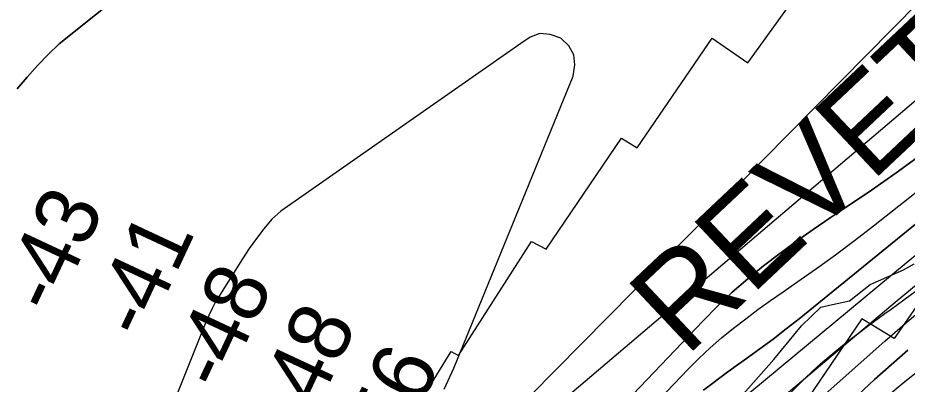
# Model space of a CAD drawing. Extents: x 3271442 to 3309282, y 752266 to 777610.
# Drawn here: x 3289820 to 3290779, y 763803 to 764198 of the extents above; entities that cross this region are included whole.
import ezdxf

# ---------------------------------------------------------------- set-up
doc = ezdxf.new("R2010")
doc.units = 0
for name, color, linetype in [('V-RIVR-EDGE', 7, 'Continuous'), ('V-RIVR-RANG', 7, 'Continuous'), ('V-RRAP-FSHR', 7, 'Continuous'), ('V-RRAP-RVMT', 7, 'Continuous'), ('V-RRAP-RVMT-IDEN', 7, 'Continuous'), ('V-TOPO-DPTH', 7, 'Continuous'), ('V-TOPO-MAJR', 7, 'Continuous'), ('V-TOPO-MINR', 7, 'Continuous'), ('V-TOPO-WATR', 7, 'Continuous')]:
    doc.layers.add(name, color=color, linetype=linetype)

msp = doc.modelspace()

# ---------------------------------------------------------------- linework, layer by layer
at = {"layer": 'V-RIVR-EDGE'}
msp.add_lwpolyline([(3290599.96, 763789.21), (3290635.27, 763829.55), (3290665.35, 763865.98), (3290686.27, 763885.93), (3290698.88, 763888.94), (3290717.15, 763892.81), (3290739.36, 763910.57), (3290775.47, 763926.13), (3290786.79, 763932.62)], dxfattribs=at)
at = {"layer": 'V-RRAP-FSHR'}
msp.add_spline([(3289175.29, 762139.24), (3289199.42, 762153.42), (3289238.78, 762167.31), (3289290.78, 762181.41), (3289361.33, 762211.47), (3289422.74, 762245.58), (3289515.55, 762307.77), (3289579.91, 762382.16), (3289624.81, 762451.54), (3289672.32, 762536.12), (3289709.18, 762613.43), (3289742.72, 762696.07), (3289778.16, 762754.9), (3289819.53, 762799.05), (3289911.37, 762921.92), (3289994.15, 763031.19), (3290081.23, 763125.2), (3290188.83, 763225.81), (3290291.39, 763333.07), (3290344.49, 763399.52), (3290388.71, 763467.2), (3290474.09, 763575.32), (3290571.03, 763693.18), (3290669.81, 763810.12), (3290775.65, 763894.02), (3290904.09, 763991.91), (3291011.39, 764077.28), (3291099.77, 764130.44), (3291153.65, 764153.45), (3291210.45, 764195.78), (3291300.74, 764249.03), (3291400.46, 764351.43), (3291483.31, 764483.33), (3291547.71, 764562.33), (3291620.77, 764622.94), (3291661.95, 764638.83), (3291706.23, 764608.33), (3291755.42, 764603.5), (3291805.88, 764628.53)], degree=3, dxfattribs=at)
at = {"layer": 'V-RRAP-RVMT'}
for points in [[(3289582.62, 762997.39), (3289626.85, 763063.65), (3289644.89, 763051.42), (3289709.27, 763155.01), (3289704.3, 763158.12), (3289783.21, 763294.08), (3289809.43, 763277.73), (3289884.41, 763395.73), (3289929.71, 763369.41), (3290001.69, 763497.83), (3290019.63, 763487.84), (3290094.58, 763611.24), (3290107.3, 763605.11), (3290184.86, 763727.23), (3290209.23, 763711.32), (3290287.31, 763838.28), (3290295.31, 763833.87), (3290373.87, 763956.68), (3290389.67, 763948.54), (3290471.14, 764068.21), (3290488.17, 764057.78), (3290568.9, 764175.9), (3290607.36, 764149.51), (3290692.59, 764267.6)], [(3290842.78, 763964.05), (3290765.31, 763852.39), (3290730.33, 763873.46), (3290651.26, 763757.1), (3290628.73, 763771.72), (3290554.34, 763656.34), (3290549.89, 763659.57), (3290471.69, 763534.96), (3290464.67, 763538.46), (3290387.65, 763416.75), (3290380.88, 763420.81), (3290304.86, 763294.94), (3290279.44, 763309.42), (3290211.6, 763193.13), (3290178.74, 763212.46), (3290105.42, 763088.04), (3290070.62, 763107.88), (3290001.82, 762986.21), (3289981.74, 762996.99), (3289899.79, 762875.03), (3289889.17, 762882.67), (3289806.67, 762757.93), (3289782.89, 762774.11)]]:
    msp.add_lwpolyline(points, dxfattribs=at)
at = {"layer": 'V-TOPO-DPTH'}
for p, q in [((3290780.02, 763839.71), (3290761.97, 763824.02)), ((3290761.97, 763824.02), (3290744.18, 763808.03)), ((3290744.18, 763808.03), (3290608.89, 763683.4))]:
    msp.add_line(p, q, dxfattribs=at)
for points in [[(3289819.2, 764121.3), (3289829.88, 764134.02), (3289840.93, 764146.44), (3289852.55, 764158.32), (3289864.54, 764169.8), (3290452.45, 764639.29)], [(3290452.45, 764639.29), (3289864.54, 764169.8), (3289852.55, 764158.32), (3289840.93, 764146.44), (3289829.88, 764134.02), (3289819.2, 764121.3)], [(3289546.72, 762768.4), (3289979.87, 763321.36), (3290007.4, 763355.22), (3290035.01, 763389), (3290062.76, 763422.68), (3290090.59, 763456.29), (3290118.71, 763489.64), (3290147.16, 763522.72), (3290176.07, 763555.38), (3290205.3, 763587.78), (3290238.78, 763624.35), (3290255.86, 763643.66), (3290272.48, 763663.35), (3290288.4, 763683.61), (3290303.86, 763704.24), (3290322.93, 763730.61), (3290328.46, 763738.38), (3290333.92, 763746.19), (3290339.27, 763754.07), (3290344.55, 763762), (3290875.23, 764299.8)], [(3290875.23, 764299.8), (3290344.55, 763762), (3290339.27, 763754.07), (3290333.92, 763746.19), (3290328.46, 763738.38), (3290322.93, 763730.61), (3290303.86, 763704.24), (3290288.4, 763683.61), (3290272.48, 763663.35), (3290255.86, 763643.66), (3290238.78, 763624.35), (3290205.3, 763587.78), (3290176.07, 763555.38), (3290147.16, 763522.72), (3290118.71, 763489.64), (3290090.59, 763456.29), (3290062.76, 763422.68), (3290035.01, 763389), (3290007.4, 763355.22), (3289979.87, 763321.36), (3289844.45, 763148.48), (3289886.98, 763122.41)], [(3290395.89, 763775.62), (3290891.68, 764197)], [(3290395.89, 763775.62), (3290891.68, 764197)], [(3290793.75, 764050.02), (3290767.39, 764030.83), (3290740.64, 764012.19), (3290713.63, 763993.9), (3290696.08, 763982.29), (3290677.8, 763969.88), (3290659.73, 763957.18), (3290641.96, 763944.06), (3290624.4, 763930.65), (3290607.32, 763916.67), (3290590.66, 763902.22), (3290574.66, 763887.05), (3290559.08, 763871.41), (3290407.9, 763712.78)], [(3290793.75, 764050.02), (3290767.39, 764030.83), (3290740.64, 764012.19), (3290713.63, 763993.9), (3290696.08, 763982.29), (3290677.8, 763969.88), (3290659.73, 763957.18), (3290641.96, 763944.06), (3290624.4, 763930.65), (3290607.32, 763916.67), (3290590.66, 763902.22), (3290574.66, 763887.05), (3290559.08, 763871.41), (3290407.9, 763712.78)], [(3290559.48, 763796.39), (3290568.23, 763803.14), (3290577.05, 763809.79), (3290585.96, 763816.32), (3290594.94, 763822.77), (3290606, 763830.58), (3290620.45, 763841), (3290634.75, 763851.61), (3290648.85, 763862.51), (3290662.8, 763873.58), (3290790.23, 763976.84)], [(3290790.23, 763976.84), (3290662.8, 763873.58), (3290648.85, 763862.51), (3290634.75, 763851.61), (3290620.45, 763841), (3290606, 763830.58), (3290594.94, 763822.77), (3290585.96, 763816.32), (3290577.05, 763809.79), (3290568.23, 763803.14), (3290559.48, 763796.39)], [(3290020.56, 763069.25), (3290038.34, 763092.48), (3290055.96, 763115.83), (3290073.53, 763139.23), (3290091.2, 763162.54), (3290109.02, 763185.75), (3290126.95, 763208.87), (3290269.57, 763391.68), (3290305.97, 763437.65), (3290342.79, 763483.28), (3290380.25, 763528.39), (3290418.14, 763573.14), (3290494.56, 763662.13), (3290766.17, 763891.28), (3290791.11, 763912.08)], [(3290020.56, 763069.25), (3290038.34, 763092.48), (3290055.96, 763115.83), (3290073.53, 763139.23), (3290091.2, 763162.54), (3290109.02, 763185.75), (3290126.95, 763208.87), (3290269.57, 763391.68), (3290305.97, 763437.65), (3290342.79, 763483.28), (3290380.25, 763528.39), (3290418.14, 763573.14), (3290494.56, 763662.13), (3290766.17, 763891.28), (3290791.11, 763912.08)]]:
    msp.add_lwpolyline(points, dxfattribs=at)
at = {"layer": 'V-TOPO-MAJR'}
for points in [[(3290419.73, 764158.12), (3290414.14, 764167.65), (3290405.54, 764176.2), (3290394, 764180.15), (3290382.89, 764180.99), (3290372.43, 764177.16), (3290362.41, 764170.22), (3290103.61, 763989.45), (3290094.04, 763980.77), (3290085.43, 763970.59), (3290077.18, 763960.15), (3290069.47, 763949.3), (3290062.11, 763938.18), (3290037.43, 763898.75), (3290033.29, 763891.74), (3290029.41, 763884.59), (3290025.93, 763877.24), (3290022.69, 763869.76), (3289954.67, 763699.99)], [(3290279.94, 763797.5), (3290290.29, 763820.38), (3290418.89, 764135.14), (3290420.81, 764147.12), (3290419.73, 764158.12)]]:
    msp.add_lwpolyline(points, dxfattribs=at)
at = {"layer": 'V-TOPO-MINR'}
for p, q in [((3290776.63, 763867.93), (3290798.15, 763886.14)), ((3290755.34, 763849.45), (3290776.63, 763867.93)), ((3290554.22, 763671.66), (3290755.34, 763849.45)), ((3290761.97, 763824.02), (3290780.02, 763839.71)), ((3290744.18, 763808.03), (3290761.97, 763824.02)), ((3290776.86, 763805.96), (3290792.16, 763818.28)), ((3290608.89, 763683.4), (3290744.18, 763808.03)), ((3290761.81, 763793.35), (3290776.86, 763805.96))]:
    msp.add_line(p, q, dxfattribs=at)
for points in [[(3290452.45, 764639.29), (3289864.54, 764169.8), (3289852.55, 764158.32), (3289840.93, 764146.44), (3289829.88, 764134.02), (3289819.2, 764121.3)], [(3289546.72, 762768.4), (3289979.87, 763321.36), (3290007.4, 763355.22), (3290035.01, 763389), (3290062.76, 763422.68), (3290090.59, 763456.29), (3290118.71, 763489.64), (3290147.16, 763522.72), (3290176.07, 763555.38), (3290205.3, 763587.78), (3290238.78, 763624.35), (3290255.86, 763643.66), (3290272.48, 763663.35), (3290288.4, 763683.61), (3290303.86, 763704.24), (3290322.93, 763730.61), (3290328.46, 763738.38), (3290333.92, 763746.19), (3290339.27, 763754.07), (3290344.55, 763762), (3290875.23, 764299.8)], [(3290395.89, 763775.62), (3290891.68, 764197)], [(3290407.9, 763712.78), (3290559.08, 763871.41), (3290574.66, 763887.05), (3290590.66, 763902.22), (3290607.32, 763916.67), (3290624.4, 763930.65), (3290641.96, 763944.06), (3290659.73, 763957.18), (3290677.8, 763969.88), (3290696.08, 763982.29), (3290713.63, 763993.9), (3290740.64, 764012.19), (3290767.39, 764030.83), (3290793.75, 764050.02)], [(3290450.02, 763721.89), (3290542.92, 763819.12), (3290554.62, 763830.84), (3290566.63, 763842.2), (3290579.12, 763853.04), (3290591.94, 763863.52), (3290605.09, 763873.61), (3290618.36, 763883.53), (3290631.82, 763893.2), (3290645.4, 763902.7), (3290660.33, 763912.93), (3290681.31, 763927.64), (3290702.09, 763942.62), (3290722.56, 763958.01), (3290742.83, 763973.69), (3290802.64, 764020.91)], [(3290559.48, 763796.39), (3290568.23, 763803.14), (3290577.05, 763809.79), (3290585.96, 763816.32), (3290594.94, 763822.77), (3290606, 763830.58), (3290620.45, 763841), (3290634.75, 763851.61), (3290648.85, 763862.51), (3290662.8, 763873.58), (3290790.23, 763976.84)], [(3290579.98, 763769.64), (3290778.08, 763933.69), (3290806.32, 763956.84)]]:
    msp.add_lwpolyline(points, dxfattribs=at)
at = {"layer": 'V-TOPO-WATR'}
msp.add_lwpolyline([(3290020.56, 763069.25), (3290038.34, 763092.48), (3290055.96, 763115.83), (3290073.53, 763139.23), (3290091.2, 763162.54), (3290109.02, 763185.75), (3290126.95, 763208.87), (3290269.57, 763391.68), (3290305.97, 763437.65), (3290342.79, 763483.28), (3290380.25, 763528.39), (3290418.14, 763573.14), (3290494.56, 763662.13), (3290766.17, 763891.28), (3290791.11, 763912.08)], dxfattribs=at)

# ---------------------------------------------------------------- texts
at = {"layer": 'V-RIVR-RANG'}
for s, p in [('-43', (3289858.75, 763875.76)), ('-41', (3289956.5, 763848.75)), ('-48', (3290040.86, 763793.06)), ('-48', (3290131.35, 763750.51)), ('-56', (3290221.18, 763706.52))]:
    msp.add_text(s, height=67, rotation=64.963, dxfattribs=at).set_placement(p)
at = {"layer": 'V-RRAP-RVMT-IDEN'}
msp.add_text('REVET.', height=100, rotation=43.29051, dxfattribs=at).set_placement((3290540.4, 763831.47))

doc.saveas('drawing.dxf')
